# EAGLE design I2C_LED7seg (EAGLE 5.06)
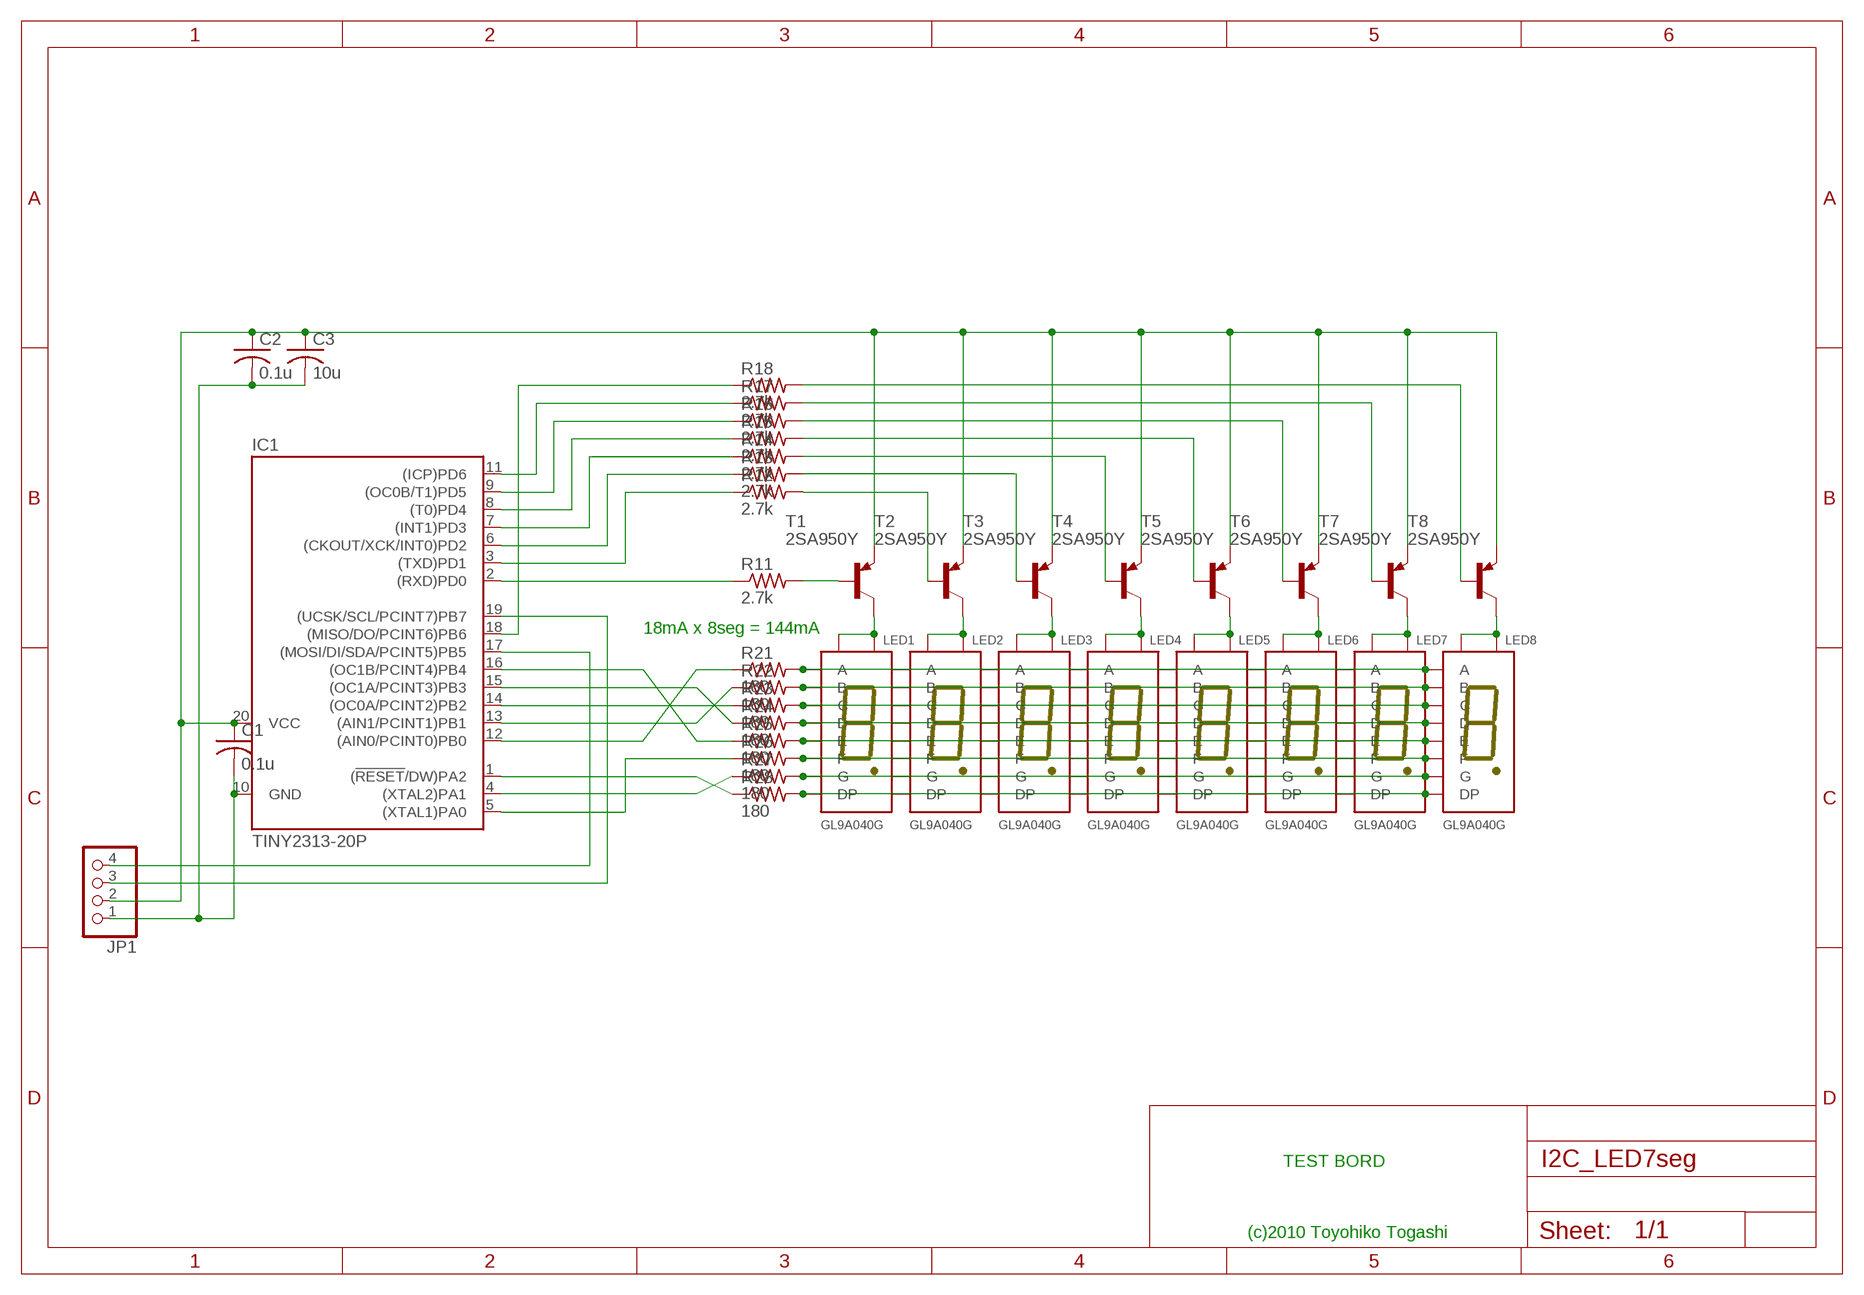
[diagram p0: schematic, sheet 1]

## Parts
C1  0.1u  C-US050-024X044  [C050-024X044]
C2  0.1u  C-US025-025X050  [C025-025X050]
C3  10u  C-US025-025X050  [C025-025X050]
IC1  TINY2313-20P  [DIL20]
JP1  PINHD-1X4  [1X04]
LED1  GL9A040G  [GL9A040G]
LED2  GL9A040G  [GL9A040G]
LED3  GL9A040G  [GL9A040G]
LED4  GL9A040G  [GL9A040G]
LED5  GL9A040G  [GL9A040G]
LED6  GL9A040G  [GL9A040G]
LED7  GL9A040G  [GL9A040G]
LED8  GL9A040G  [GL9A040G]
R11  2.7k  R-US_0204/7  [0204/7]
R12  2.7k  R-US_0204/7  [0204/7]
R13  2.7k  R-US_0204/7  [0204/7]
R14  2.7k  R-US_0204/7  [0204/7]
R15  2.7k  R-US_0204/7  [0204/7]
R16  2.7k  R-US_0204/7  [0204/7]
R17  2.7k  R-US_0204/7  [0204/7]
R18  2.7k  R-US_0204/7  [0204/7]
R21  180  R-US_0204/5  [0204/5]
R22  180  R-US_0204/5  [0204/5]
R23  180  R-US_0204/5  [0204/5]
R24  180  R-US_0204/5  [0204/5]
R25  180  R-US_0204/5  [0204/5]
R26  180  R-US_0204/5  [0204/5]
R27  180  R-US_0204/5  [0204/5]
R28  180  R-US_0204/5  [0204/5]
T1  2SA950Y  2SC1815-PNP-TO92-BCE  [TO92-BCE]
T2  2SA950Y  2SC1815-PNP-TO92-BCE  [TO92-BCE]
T3  2SA950Y  2SC1815-PNP-TO92-BCE  [TO92-BCE]
T4  2SA950Y  2SC1815-PNP-TO92-BCE  [TO92-BCE]
T5  2SA950Y  2SC1815-PNP-TO92-BCE  [TO92-BCE]
T6  2SA950Y  2SC1815-PNP-TO92-BCE  [TO92-BCE]
T7  2SA950Y  2SC1815-PNP-TO92-BCE  [TO92-BCE]
T8  2SA950Y  2SC1815-PNP-TO92-BCE  [TO92-BCE]

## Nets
N$2: LED1.P$10(A) LED2.P$10(A) LED3.P$10(A) LED4.P$10(A) LED5.P$10(A) LED6.P$10(A) LED7.P$10(A) LED8.P$10(A) R21.2
N$3: IC1.19((UCSK/SCL/PCINT7)PB7) JP1.3
N$4: IC1.17((MOSI/DI/SDA/PCINT5)PB5) JP1.4
N$5: C1.1 C2.1 C3.1 IC1.20(VCC) JP1.2 T1.E T2.E T3.E T4.E T5.E T6.E T7.E T8.E
N$6: LED1.P$9(B) LED2.P$9(B) LED3.P$9(B) LED4.P$9(B) LED5.P$9(B) LED6.P$9(B) LED7.P$9(B) LED8.P$9(B) R22.2
N$7: LED1.P$8(C) LED2.P$8(C) LED3.P$8(C) LED4.P$8(C) LED5.P$8(C) LED6.P$8(C) LED7.P$8(C) LED8.P$8(C) R23.2
N$8: LED1.P$5(D) LED2.P$5(D) LED3.P$5(D) LED4.P$5(D) LED5.P$5(D) LED6.P$5(D) LED7.P$5(D) LED8.P$5(D) R24.2
N$9: LED1.P$4(E) LED2.P$4(E) LED3.P$4(E) LED4.P$4(E) LED5.P$4(E) LED6.P$4(E) LED7.P$4(E) LED8.P$4(E) R25.2
N$10: LED1.P$2(F) LED2.P$2(F) LED3.P$2(F) LED4.P$2(F) LED5.P$2(F) LED6.P$2(F) LED7.P$2(F) LED8.P$2(F) R26.2
N$11: LED1.P$7(DP) LED2.P$7(DP) LED3.P$7(DP) LED4.P$7(DP) LED5.P$7(DP) LED6.P$7(DP) LED7.P$7(DP) LED8.P$7(DP) R28.2
N$12: LED1.P$3(G) LED2.P$3(G) LED3.P$3(G) LED4.P$3(G) LED5.P$3(G) LED6.P$3(G) LED7.P$3(G) LED8.P$3(G) R27.2
N$13: R11.2 T1.B
N$14: IC1.5((XTAL1)PA0) R26.1
N$15: IC1.4((XTAL2)PA1) R27.1
N$16: IC1.1((!RESET!/DW)PA2) R28.1
N$17: IC1.12((AIN0/PCINT0)PB0) R21.1
N$18: LED1.P$1(CA1) LED1.P$6(CA6) T1.C
N$19: IC1.13((AIN1/PCINT1)PB1) R22.1
N$20: IC1.14((OC0A/PCINT2)PB2) R23.1
N$21: IC1.15((OC1A/PCINT3)PB3) R24.1
N$22: IC1.16((OC1B/PCINT4)PB4) R25.1
N$23: LED2.P$1(CA1) LED2.P$6(CA6) T2.C
N$24: LED3.P$1(CA1) LED3.P$6(CA6) T3.C
N$25: IC1.2((RXD)PD0) R11.1
N$26: R18.2 T8.B
N$27: LED4.P$1(CA1) LED4.P$6(CA6) T4.C
N$28: IC1.18((MISO/DO/PCINT6)PB6) R18.1
N$29: LED5.P$1(CA1) LED5.P$6(CA6) T5.C
N$30: LED6.P$1(CA1) LED6.P$6(CA6) T6.C
N$31: LED7.P$1(CA1) LED7.P$6(CA6) T7.C
N$32: LED8.P$1(CA1) LED8.P$6(CA6) T8.C
N$33: C1.2 C2.2 C3.2 IC1.10(GND) JP1.1
N$35: R12.2 T2.B
N$48: R13.2 T3.B
N$60: R14.2 T4.B
N$72: R15.2 T5.B
N$84: R16.2 T6.B
N$96: R17.2 T7.B
N$98: IC1.3((TXD)PD1) R12.1
N$99: IC1.6((CKOUT/XCK/INT0)PD2) R13.1
N$100: IC1.7((INT1)PD3) R14.1
N$101: IC1.8((T0)PD4) R15.1
N$102: IC1.9((OC0B/T1)PD5) R16.1
N$103: IC1.11((ICP)PD6) R17.1

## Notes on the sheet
- 18mA x 8seg = 144mA
- TEST BORD
- (c)2010 Toyohiko Togashi

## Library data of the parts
C1-C3 = rcl:C-US: CAPACITOR, American symbol
IC1 = TOG:TINY2313: 8-bit AVR Microcontroller with 2K Bytes Flash Source: http://www.atmel.com .. doc2543.pdf
JP1 = pinhead:PINHD-1X4: PIN HEADER
LED1-LED8 = TOG:GL9A040G: 7 Segment LED
R11-R18 R21-R28 = rcl:R-US_: RESISTOR, American symbol
T1-T8 = transistor:*-PNP-: PNP Transistror

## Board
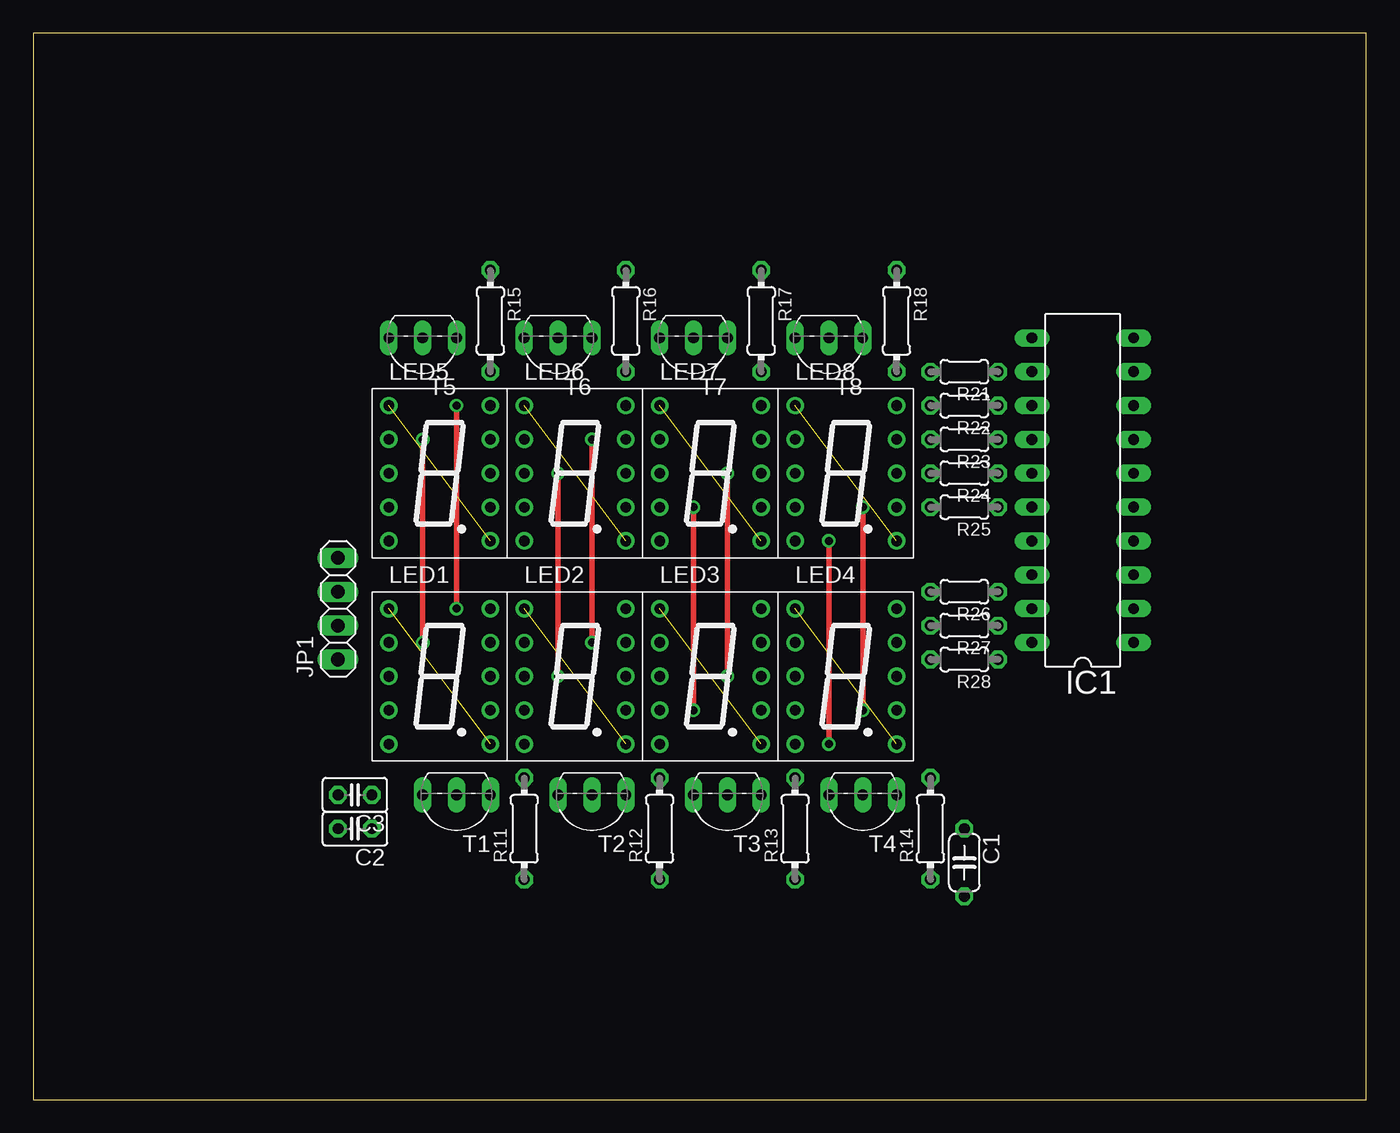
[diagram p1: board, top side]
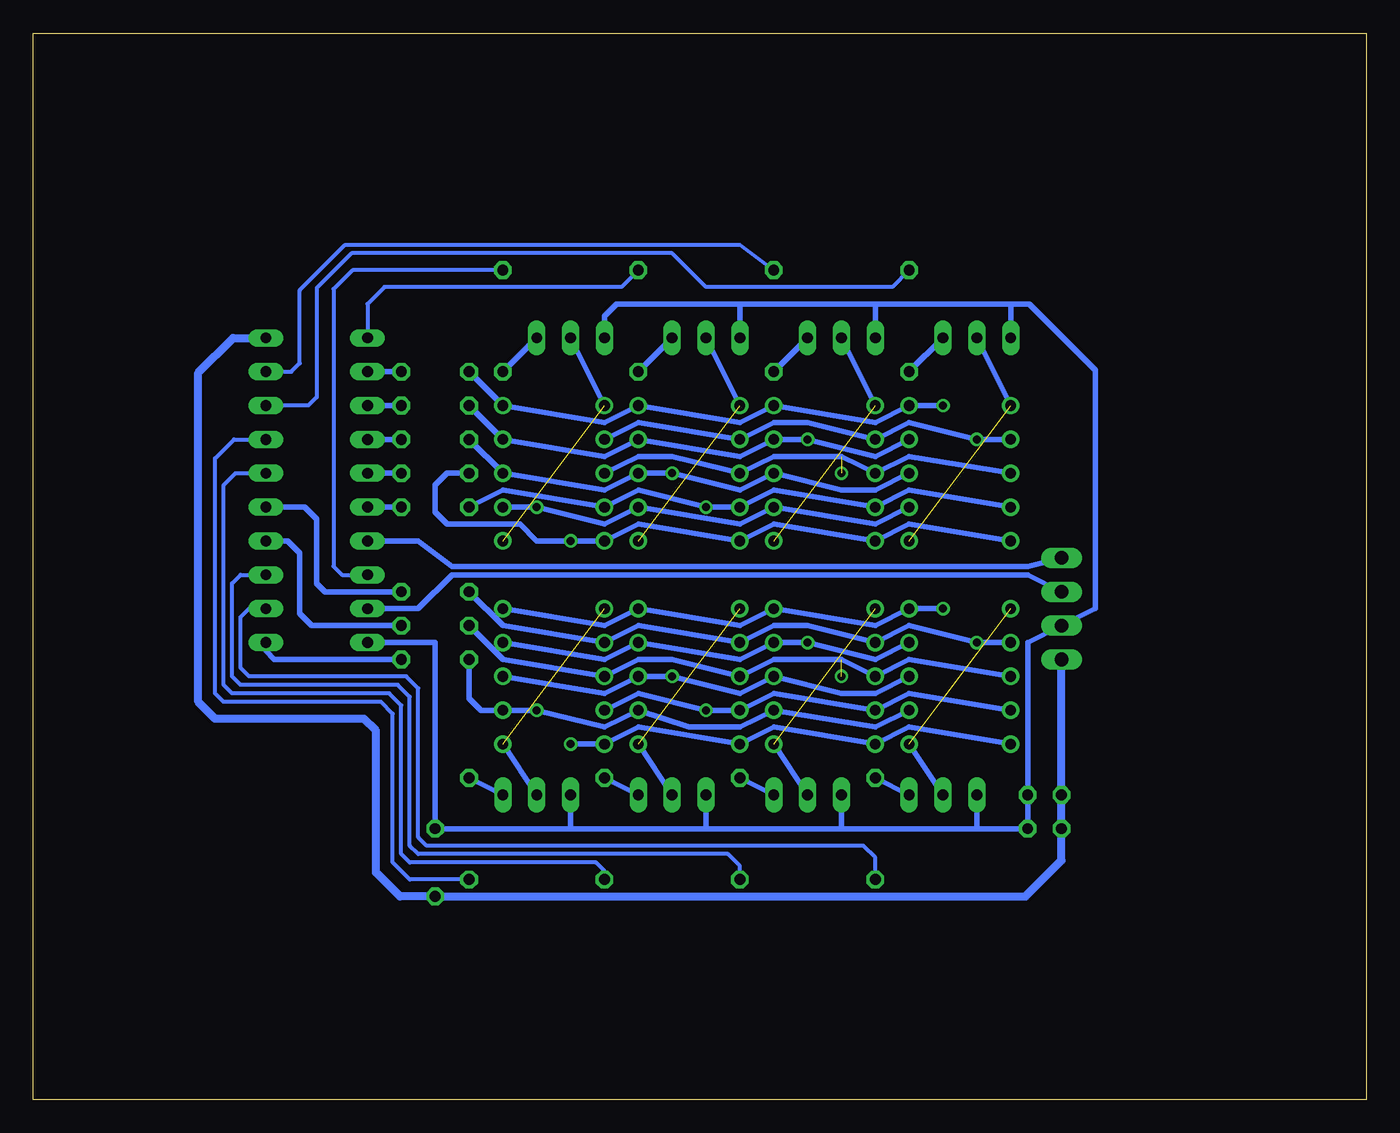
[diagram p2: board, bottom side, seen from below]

Size 100 x 80 mm. Coordinates in mm from the lower left corner, seen from the top.
Outline: 0,0 100,0 100,80 0,80 0,0
Copper layers (1*16): Top 0.035mm / dielectric 1.5mm / Bottom 0.035mm
Design rules "default": minimum track width 10mil, minimum drill 24mil, track to track 8mil, track to pad 8mil, pad to pad 8mil, via to via 8mil, smd to smd 8mil, copper to edge 40mil, drill to drill 8mil, minimum pad ring 10mil, minimum via ring 8mil, stop-mask expansion 4mil, vias tented up to drill 0mil, thermal gap 10mil

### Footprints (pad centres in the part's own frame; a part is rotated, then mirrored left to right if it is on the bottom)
C050-024X044 = drill 0.813 octagon: 1 -2.54,0; 2 2.54,0
C025-025X050 = drill 0.813 octagon: 1 -1.27,0; 2 1.27,0
DIL20 = drill 0.813 long: 1 -11.43,-3.81; 2 -8.89,-3.81; 3 -6.35,-3.81; 4 -3.81,-3.81; 5 -1.27,-3.81; 6 1.27,-3.81; 7 3.81,-3.81; 8 6.35,-3.81; 9 8.89,-3.81; 10 11.43,-3.81; 11 11.43,3.81; 12 8.89,3.81; 13 6.35,3.81; 14 3.81,3.81; 15 1.27,3.81; 16 -1.27,3.81; 17 -3.81,3.81; 18 -6.35,3.81; 19 -8.89,3.81; 20 -11.43,3.81
1X04 = drill 1.016 long: 1 -3.81,0; 2 -1.27,0; 3 1.27,0; 4 3.81,0
GL9A040G = drill 0.8 round: P$1 -3.81,5.08; P$2 -3.81,2.54; P$3 -3.81,0; P$4 -3.81,-2.54; P$5 -3.81,-5.08; P$6 3.81,-5.08; P$7 3.81,-2.54; P$8 3.81,0; P$9 3.81,2.54; P$10 3.81,5.08
0204/7 = drill 0.813 octagon: 1 -3.81,0; 2 3.81,0
0204/5 = drill 0.813 octagon: 1 -2.54,0; 2 2.54,0
TO92-BCE = drill 0.813 long: B -2.54,0; C 0,0; E 2.54,0

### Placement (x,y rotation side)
C1  69.85,17.78 270 top
C2  24.13,20.32 180 top
C3  24.13,22.86 180 top
IC1  78.74,45.72 90 top
JP1  22.86,36.83 90 top
LED1  30.48,31.75 0 top
LED2  40.64,31.75 0 top
LED3  50.8,31.75 0 top
LED4  60.96,31.75 0 top
LED5  30.48,46.99 0 top
LED6  40.64,46.99 0 top
LED7  50.8,46.99 0 top
LED8  60.96,46.99 0 top
R11  36.83,20.32 90 top
R12  46.99,20.32 90 top
R13  57.15,20.32 90 top
R14  67.31,20.32 90 top
R15  34.29,58.42 270 top
R16  44.45,58.42 270 top
R17  54.61,58.42 270 top
R18  64.77,58.42 270 top
R21  69.85,54.61 180 top
R22  69.85,52.07 180 top
R23  69.85,49.53 180 top
R24  69.85,46.99 180 top
R25  69.85,44.45 180 top
R26  69.85,38.1 180 top
R27  69.85,35.56 180 top
R28  69.85,33.02 180 top
T1  31.75,22.86 180 top
T2  41.91,22.86 180 top
T3  52.07,22.86 180 top
T4  62.23,22.86 180 top
T5  29.21,57.15 180 top
T6  39.37,57.15 180 top
T7  49.53,57.15 180 top
T8  59.69,57.15 180 top

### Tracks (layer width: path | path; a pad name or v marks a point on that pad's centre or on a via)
N$2  (via drill 0.6)
  Top 0.406: v31.75,36.83 v31.75,52.07
  Bottom 0.406: v31.75,36.83 LED1.P$10 36.83,35.56 LED2.P$10 46.99,35.56 LED3.P$10 57.15,35.56 LED4.P$10 | v31.75,52.07 LED5.P$10 36.83,50.8 LED6.P$10 46.99,50.8 LED7.P$10 57.15,50.8 LED8.P$10 R21.2
N$3
  Bottom 0.406: IC1.19 71.12,36.83 68.58,39.37 25.4,39.37 JP1.3
N$4
  Bottom 0.406: IC1.17 71.12,41.91 68.58,40.01 25.4,40.01 JP1.4
N$5
  Bottom 0.406: IC1.20 69.85,34.29 C1.1 59.69,20.32 | 29.21,20.32 39.37,20.32 | 39.37,20.32 49.53,20.32 | 49.53,20.32 59.69,20.32 | 29.21,20.32 T1.E | 39.37,20.32 T2.E | 49.53,20.32 T3.E | 59.69,20.32 T4.E | 26.67,59.69 25.28,59.69 20.32,54.73 20.32,36.83 JP1.2 25.4,34.29 C2.1 | 26.67,59.69 36.83,59.69 | 36.83,59.69 46.99,59.69 | 46.99,59.69 56.25,59.69 57.15,58.79 T8.E | C2.1 29.21,20.32 | C2.1 C3.1 | 26.67,59.69 T5.E | 36.83,59.69 T6.E | 46.99,59.69 T7.E
N$6  (via drill 0.6)
  Top 0.406: v41.91,34.29 v41.91,49.53
  Bottom 0.406: LED4.P$9 57.15,33.02 LED3.P$9 46.99,33.02 LED2.P$9 v41.91,34.29 36.83,33.02 LED1.P$9 | LED5.P$9 36.83,48.26 v41.91,49.53 LED6.P$9 46.99,48.26 LED7.P$9 57.15,48.26 LED8.P$9 R22.2
N$7  (via drill 0.6)
  Top 0.406: v52.07,31.75 v52.07,46.99
  Bottom 0.406: LED1.P$8 36.83,30.48 39.37,30.48 LED2.P$8 46.99,30.48 v52.07,31.75 LED3.P$8 57.15,30.48 LED4.P$8 | LED5.P$8 36.83,45.72 39.37,45.72 LED6.P$8 46.99,45.72 v52.07,46.99 LED7.P$8 57.15,45.72 LED8.P$8 R23.2
N$8  (via drill 0.6)
  Top 0.406: v59.69,26.67 v59.69,41.91
  Bottom 0.406: LED1.P$5 34.29,27.94 LED2.P$5 44.45,27.94 LED3.P$5 54.61,27.94 LED4.P$5 v59.69,26.67 | LED5.P$5 34.29,43.18 LED6.P$5 44.45,43.18 LED7.P$5 54.61,43.18 LED8.P$5 v59.69,41.91 62.23,41.91 63.5,43.18 68.95,43.18 69.85,44.08 69.85,46.09 68.95,46.99 R24.2
N$9  (via drill 0.6)
  Top 0.406: v49.53,29.21 v49.53,44.45
  Bottom 0.406: LED1.P$4 34.29,30.48 LED2.P$4 44.45,30.48 LED3.P$4 v49.53,29.21 54.61,30.48 LED4.P$4 | LED5.P$4 34.29,45.72 LED6.P$4 44.45,45.72 LED7.P$4 v49.53,44.45 54.61,45.72 LED8.P$4 64.77,45.72 R25.2
N$10  (via drill 0.6)
  Top 0.406: v29.21,34.29 v29.21,49.53
  Bottom 0.406: LED1.P$2 v29.21,34.29 34.29,35.56 LED2.P$2 41.91,35.56 44.45,35.56 LED3.P$2 54.61,35.56 LED4.P$2 64.77,35.56 R26.2 | LED5.P$2 v29.21,49.53 34.29,50.8 LED6.P$2 41.91,50.8 44.45,50.8 LED7.P$2 54.61,50.8 LED8.P$2
N$11  (via drill 0.6)
  Top 0.406: v62.23,29.21 v62.23,44.45
  Bottom 0.406: LED1.P$7 36.83,27.94 LED2.P$7 46.99,27.94 50.8,27.94 LED3.P$7 57.15,27.94 v62.23,29.21 LED4.P$7 66.41,29.21 67.31,30.11 R28.2 | LED5.P$7 36.83,43.18 LED6.P$7 46.99,43.18 LED7.P$7 57.15,43.18 v62.23,44.45 LED8.P$7
N$12  (via drill 0.6)  (2 unrouted)
  Top 0.406: v39.37,31.75 v39.37,46.99
  Bottom 0.406: LED1.P$3 34.29,33.02 LED2.P$3 39.37,33.02 44.45,33.02 LED3.P$3 52.07,33.02 54.61,33.02 LED4.P$3 64.77,33.02 R27.2 | LED5.P$3 34.29,48.26 LED6.P$3 39.37,48.26 44.45,48.26 LED7.P$3 52.07,48.26 54.61,48.26 LED8.P$3
N$13
  Bottom 0.406: T1.B R11.2
N$14
  Bottom 0.406: R26.1 78.11,38.1 78.74,38.73 78.74,43.55 79.64,44.45 IC1.5
N$15
  Bottom 0.406: R27.1 79.11,35.56 80.01,36.46 80.01,41.01 80.91,41.91 IC1.4
N$16
  Bottom 0.406: R28.1 81.92,33.02 82.55,33.66 IC1.1
N$17
  Bottom 0.406: R21.1 IC1.12
N$18  (1 unrouted)
  Bottom 0.406: T1.C LED1.P$6
N$19
  Bottom 0.406: R22.1 IC1.13
N$20
  Bottom 0.406: R23.1 IC1.14
N$21
  Bottom 0.406: R24.1 IC1.15
N$22
  Bottom 0.406: R25.1 IC1.16
N$23  (1 unrouted)
  Bottom 0.406: T2.C LED2.P$6
N$24  (1 unrouted)
  Bottom 0.406: T3.C LED3.P$6
N$25
  Bottom 0.305: R11.1 36.83,18.15 37.73,19.05 70.48,19.05 71.12,19.68 71.12,30.85 72.02,31.75 83.82,31.75 84.45,32.38 84.45,36.2 83.82,36.83 IC1.2
N$26
  Bottom 0.406: R18.2 T8.B
N$27  (1 unrouted)
  Bottom 0.406: T4.C LED4.P$6
N$28
  Bottom 0.305: R18.1 76.05,62.23 77.47,60.81 77.47,40.01 76.83,39.37 IC1.18
N$29  (1 unrouted)
  Bottom 0.406: T5.C LED5.P$1
N$30  (1 unrouted)
  Bottom 0.406: T6.C LED6.P$1
N$31  (1 unrouted)
  Bottom 0.406: T7.C LED7.P$1
N$32  (1 unrouted)
  Bottom 0.406: T8.C LED8.P$1
N$33
  Bottom 0.61: JP1.1 C3.2 C2.2 22.86,17.93 25.55,15.24 C1.2 72.5,15.24 74.3,17.04 74.3,27.68 75.19,28.57 86.36,28.57 87.63,29.84 87.63,54.53 85.01,57.15 IC1.10
N$35
  Bottom 0.406: T2.B R12.2
N$48
  Bottom 0.406: T3.B R13.2
N$60
  Bottom 0.406: R14.2 T4.B
N$72
  Bottom 0.406: T5.B R15.2
N$84
  Bottom 0.406: T6.B R16.2
N$96
  Bottom 0.406: T7.B R17.2
N$98
  Bottom 0.305: R12.1 46.99,17.52 47.89,18.41 71.12,18.41 71.75,19.05 71.75,30.22 72.65,31.11 84.45,31.11 85.09,31.75 85.09,38.73 84.45,39.37 IC1.3
N$99
  Bottom 0.305: R13.1 57.15,17.14 57.78,17.78 71.75,17.78 72.39,18.41 72.39,29.58 73.29,30.48 85.09,30.48 85.72,31.11 85.72,46.09 84.83,46.99 IC1.6
N$100
  Bottom 0.305: R14.1 71.75,16.51 73.03,17.78 73.03,28.95 73.92,29.84 85.72,29.84 86.36,30.48 86.36,48.11 84.94,49.53 IC1.7
N$101
  Bottom 0.305: R15.1 35.56,60.96 49.53,60.96 52.07,63.5 76.12,63.5 78.74,60.88 78.74,52.7 79.38,52.07 IC1.8
N$102
  Bottom 0.305: IC1.9 80.64,54.61 80.01,55.24 80.01,60.72 76.59,64.14 46.99,64.14 R16.1
N$103
  Bottom 0.305: R17.1 55.88,60.96 73.66,60.96 74.93,59.69 IC1.11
